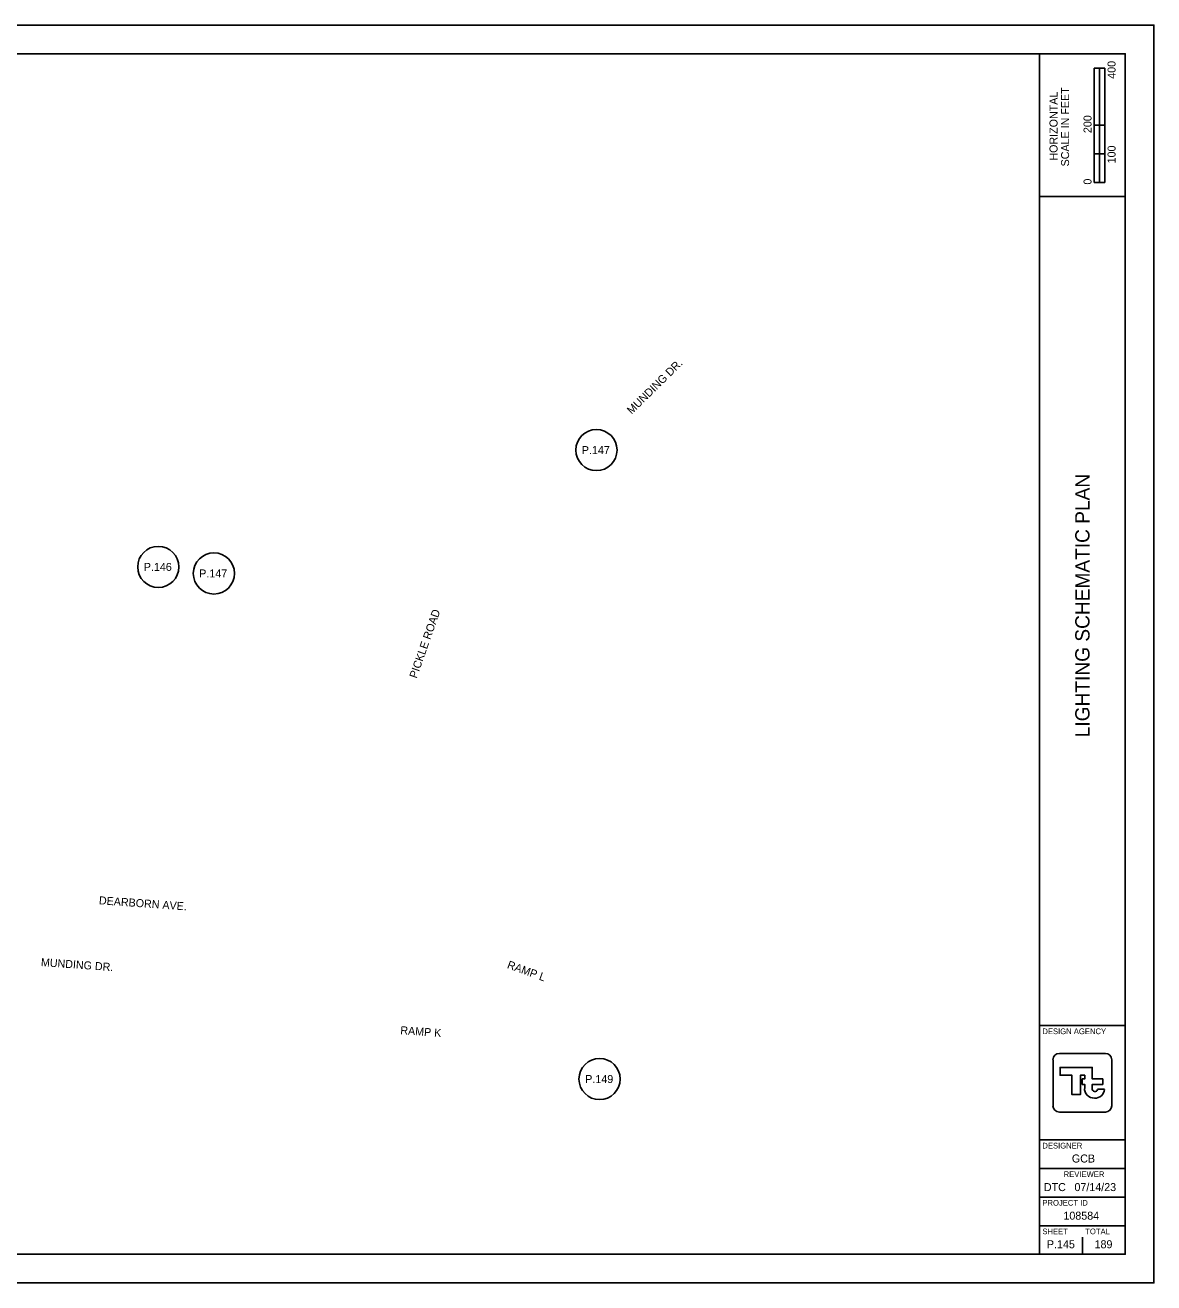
# Model space of a CAD drawing. Extents: x -5.8 to 34, y 0 to 22.
# Drawn here: x 14.25 to 34, y 0 to 22 of the extents above; entities that cross this region are included whole.
import ezdxf

# ---------------------------------------------------------------- set-up
doc = ezdxf.new("R2010")
doc.units = 0
for name, color, linetype in [('PF_X_Ground_Line', 7, 'Continuous'), ('SH_Border', 7, 'Continuous'), ('SH_Cut_Line', 7, 'Continuous'), ('SH_Data', 7, 'Continuous'), ('SH_Text', 7, 'Continuous')]:
    doc.layers.add(name, color=color, linetype=linetype)

msp = doc.modelspace()

# ---------------------------------------------------------------- linework, layer by layer
at = {"layer": 'SH_Border'}
for p, q in [((32, 0.5), (32, 21.5)), ((32, 19), (33.5, 19)), ((32, 4.5), (33.5, 4.5)), ((32, 2.5), (33.5, 2.5)), ((32, 2), (33.5, 2)), ((32, 1.5), (33.5, 1.5)), ((32, 1), (33.5, 1))]:
    msp.add_line(p, q, dxfattribs=at)
msp.add_lwpolyline([(1.5, 21.5), (33.5, 21.5), (33.5, 0.5), (1.5, 0.5)], close=True, dxfattribs=at)
at = {"layer": 'SH_Cut_Line'}
msp.add_lwpolyline([(0, 0), (34, 0), (34, 22), (0, 22)], close=True, dxfattribs=at)
at = {"layer": 'SH_Data'}
for p, q in [((32.957, 19.25), (32.957, 21.25)), ((33.144, 21.25), (32.957, 21.25)), ((32.957, 20.25), (32.957, 21.25)), ((32.957, 21.25), (33.05, 21.25)), ((33.05, 21.25), (33.051, 21.25)), ((33.051, 21.25), (33.051, 20.25)), ((33.144, 21.25), (33.144, 19.25)), ((33.051, 20.25), (32.957, 20.25)), ((33.143, 20.25), (33.05, 20.25)), ((33.05, 20.25), (33.05, 19.75)), ((33.143, 19.75), (33.143, 20.25)), ((33.05, 19.75), (32.957, 19.75)), ((32.957, 19.75), (32.957, 19.25)), ((33.05, 19.75), (33.143, 19.75)), ((33.05, 19.25), (33.05, 19.75)), ((33.144, 19.25), (32.957, 19.25)), ((32.957, 19.25), (33.05, 19.25)), ((32.75, 3.5), (32.75, 3.5)), ((32.791, 3.415), (32.791, 3.415)), ((32.791, 3.415), (32.791, 3.415)), ((33.136, 3.385), (33.015, 3.385)), ((33.136, 3.385), (33.015, 3.385)), ((32.375, 0.675), (32.375, 0.675)), ((32.75, 0.5), (32.75, 0.8))]:
    msp.add_line(p, q, dxfattribs=at)
for points in [[(32.348, 4.014), (33.152, 4.014)], [(32.348, 4.014), (33.152, 4.014)], [(32.236, 3.099), (32.236, 3.901)], [(32.236, 3.099), (32.236, 3.901)], [(32.922, 3.399), (32.922, 3.47), (33.107, 3.47), (33.107, 3.568), (32.922, 3.568), (32.922, 3.768), (32.361, 3.768), (32.361, 3.632), (32.566, 3.632), (32.566, 3.294), (32.715, 3.294), (32.715, 3.63), (32.79, 3.63), (32.79, 3.568), (32.748, 3.568), (32.748, 3.47), (32.79, 3.47), (32.79, 3.415), (32.791, 3.415)], [(32.922, 3.399), (32.922, 3.47), (33.107, 3.47), (33.107, 3.568), (32.922, 3.568), (32.922, 3.768), (32.361, 3.768), (32.361, 3.632), (32.566, 3.632), (32.566, 3.294), (32.715, 3.294), (32.715, 3.63), (32.79, 3.63), (32.79, 3.568), (32.748, 3.568), (32.748, 3.47), (32.79, 3.47), (32.79, 3.415), (32.791, 3.415)], [(33.264, 3.901), (33.264, 3.099)], [(33.264, 3.901), (33.264, 3.099)], [(33.152, 2.986), (32.348, 2.986)], [(33.152, 2.986), (32.348, 2.986)]]:
    msp.add_lwpolyline(points, dxfattribs=at)
for centre, radius, start, end in [((32.348, 3.901), 0.113, 90, 180), ((32.348, 3.901), 0.113, 90, 180), ((33.152, 3.901), 0.113, 360, 90), ((33.152, 3.901), 0.113, 360, 90), ((32.949, 3.392), 0.16, 171.8856, 274.8323), ((32.949, 3.392), 0.16, 171.8856, 274.8323), ((32.968, 3.392), 0.0473, 171.8856, 350.9243), ((32.968, 3.392), 0.0473, 171.8856, 350.9243), ((32.976, 3.392), 0.16, 265.1677, 357.3201), ((32.976, 3.392), 0.16, 265.1677, 357.3201), ((32.348, 3.099), 0.113, 180, 270), ((32.348, 3.099), 0.113, 180, 270), ((33.152, 3.099), 0.113, 270, 360), ((33.152, 3.099), 0.113, 270, 360)]:
    msp.add_arc(centre, radius, start, end, dxfattribs=at)
at = {"layer": 'SH_Text'}
for centre in [(24.249, 14.567), (16.583, 12.523), (17.556, 12.409), (24.303, 3.565)]:
    msp.add_circle(centre, 0.36, dxfattribs=at)

# ---------------------------------------------------------------- texts
at = {"layer": 'PF_X_Ground_Line'}
for s, rotation, p in [('MUNDING DR.', 44.5372, (24.864, 15.184)), ('PICKLE ROAD', 70.6704, (21.103, 10.564)), ('DEARBORN AVE.', 355.9615, (15.541, 6.623)), ('MUNDING DR.', 355.9615, (14.526, 5.541)), ('RAMP L', 340.0278, (22.675, 5.509)), ('RAMP K', 355.9615, (20.814, 4.351))]:
    msp.add_text(s, height=0.14, rotation=rotation, dxfattribs=at).set_placement(p)
at = {"layer": 'SH_Data'}
for s, height, p in [('400', 0.14, (33.33, 21.062)), ('SCALE IN FEET', 0.14, (32.517, 19.529)), ('HORIZONTAL', 0.14, (32.315, 19.63)), ('200', 0.14, (32.91, 20.112)), ('100', 0.14, (33.33, 19.582)), ('0', 0.14, (32.91, 19.211)), ('LIGHTING SCHEMATIC PLAN', 0.25, (32.875, 9.544))]:
    msp.add_text(s, height=height, rotation=90, dxfattribs=at).set_placement(p)
for s, height, p in [('DESIGN AGENCY', 0.1, (32.05, 4.35)), ('DESIGNER', 0.1, (32.05, 2.35)), ('GCB', 0.14, (32.566, 2.105)), ('REVIEWER', 0.1, (32.422, 1.85)), ('DTC', 0.14, (32.076, 1.605)), ('07/14/23', 0.14, (32.611, 1.605)), ('PROJECT ID', 0.1, (32.05, 1.35)), ('108584', 0.14, (32.418, 1.105)), ('SHEET', 0.1, (32.05, 0.85)), ('TOTAL', 0.1, (32.8, 0.85)), ('P.145', 0.14, (32.129, 0.605)), ('189', 0.14, (32.963, 0.605))]:
    msp.add_text(s, height=height, dxfattribs=at).set_placement(p)
at = {"layer": 'SH_Text'}
for s, p in [('P.147', (23.993, 14.497)), ('P.146', (16.33, 12.453)), ('P.147', (17.3, 12.339)), ('P.149', (24.053, 3.495))]:
    msp.add_text(s, height=0.14, dxfattribs=at).set_placement(p)

doc.saveas('drawing.dxf')
